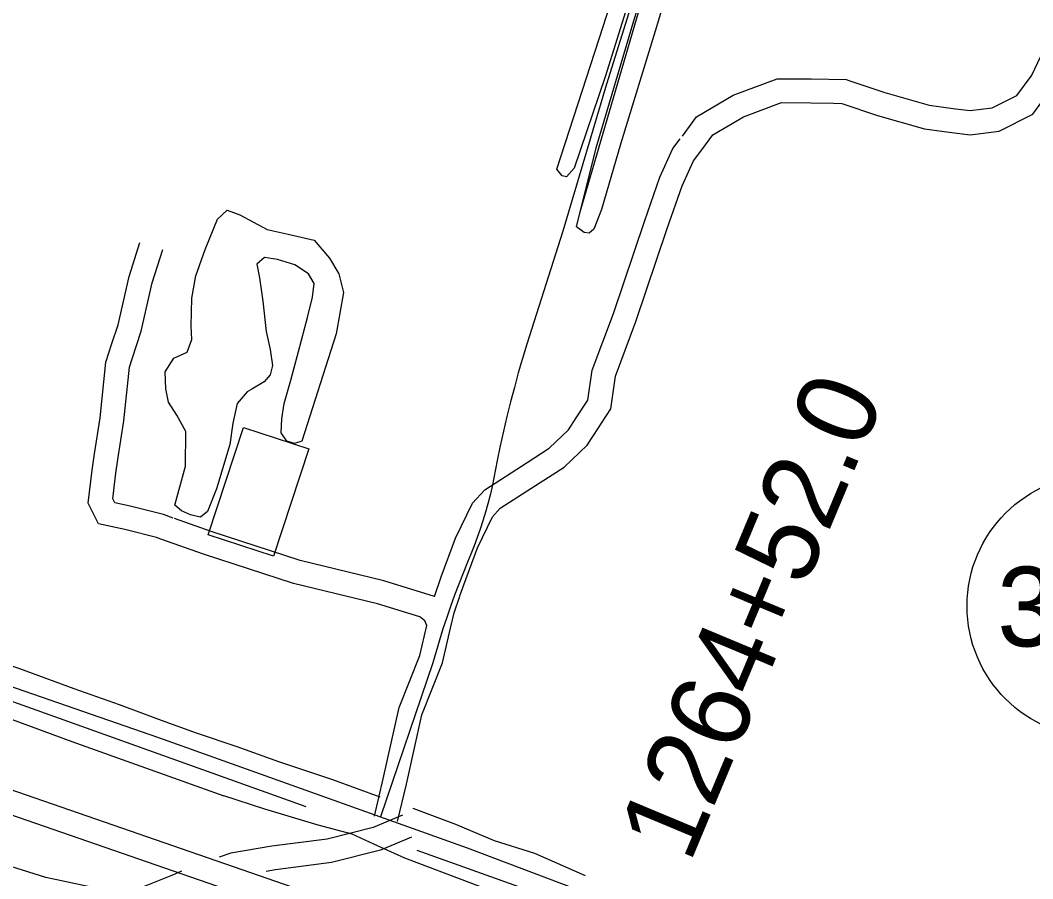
# Model space of a CAD drawing. Extents: x 3329332 to 3367211, y 631066 to 656469.
# Drawn here: x 3335657 to 3336928, y 650194 to 651272 of the extents above; entities that cross this region are included whole.
import ezdxf

# ---------------------------------------------------------------- set-up
doc = ezdxf.new("R2010")
doc.units = 0
for name, color, linetype in [('V-BLDG-OTLN', 7, 'Continuous'), ('V-DTCH-CNTR', 7, 'Continuous'), ('V-LEVE-TOET', 7, 'Continuous'), ('V-ROAD-CNTR', 7, 'Continuous'), ('V-ROAD-IDEN', 7, 'Continuous'), ('V-SITE-VEGE', 7, 'Continuous'), ('V-SURV-IDEN', 7, 'Continuous'), ('V-SURV-LINE', 7, 'Continuous'), ('V-TOPO-SHOR', 7, 'Continuous')]:
    doc.layers.add(name, color=color, linetype=linetype)

msp = doc.modelspace()

# ---------------------------------------------------------------- linework, layer by layer
at = {"layer": 'V-BLDG-OTLN'}
msp.add_lwpolyline([(3336019.4, 650733.7), (3335975.2, 650599), (3335893.1, 650626), (3335937.3, 650760.7)], close=True, dxfattribs=at)
at = {"layer": 'V-DTCH-CNTR'}
msp.add_lwpolyline([(3336472.2, 651444.9), (3336393.1, 651191.8), (3336338.4, 651007), (3336293, 650865.2), (3336287.6, 650847.2), (3336282.4, 650829), (3336277.5, 650810.9), (3336272.7, 650792.6), (3336268.2, 650774.4), (3336263.8, 650756), (3336259.7, 650737.6), (3336255.8, 650719.2), (3336253.9, 650708.2), (3336251.8, 650697.3), (3336249.5, 650686.5), (3336247, 650675.6), (3336244.2, 650664.9), (3336241.2, 650654.1), (3336238, 650643.5), (3336234.6, 650632.9), (3336230.9, 650622.4), (3336227.1, 650612), (3336223, 650601.6), (3336218.7, 650591.4), (3336213.1, 650577.6), (3336207.6, 650563.8), (3336202.4, 650549.9), (3336197.3, 650535.9), (3336192.5, 650521.9), (3336187.8, 650507.8), (3336183.3, 650493.6), (3336179.1, 650479.4), (3336175, 650465.1), (3336109.6, 650271.9)], dxfattribs=at)
at = {"layer": 'V-LEVE-TOET'}
for points in [[(3333435.4, 650905.5), (3333585.5, 650897.7), (3333679, 650879.4), (3333768.5, 650850.9), (3333895.5, 650811.2), (3334038.8, 650770.5), (3334147.6, 650739.9), (3334262.4, 650708.4), (3334325.5, 650698.2), (3334402.7, 650693.1), (3334513.5, 650701.2), (3334625.3, 650703.1), (3334696.5, 650699.1), (3334786, 650683.8), (3334902.8, 650653.2), (3335067.5, 650597.3), (3335296.2, 650516.9), (3335501.5, 650447.7), (3335722.1, 650366.3), (3335912.8, 650298.1)], [(3337615.2, 649642.5), (3337494.6, 649685.7), (3337361.8, 649739), (3337202.4, 649801.2), (3337090.8, 649845), (3336945.2, 649905.4), (3336818.8, 649959), (3336694.4, 650007.5), (3336566.9, 650058.3), (3336448, 650103.2), (3336336.5, 650145), (3336224.2, 650188.1), (3336140.1, 650219.9), (3336101.2, 650237.5), (3336073.8, 650249.9), (3336031, 650261.3), (3335964.3, 650281.5), (3335912.8, 650298.1)], [(3335931.9, 650111.7), (3335881.1, 650129), (3335824.2, 650142.3), (3335802.9, 650151.4), (3335795.2, 650156.8), (3335789.1, 650172.1), (3335771.8, 650178.2), (3335689.5, 650195.5), (3335557.3, 650237.2)]]:
    msp.add_lwpolyline(points, dxfattribs=at)
at = {"layer": 'V-ROAD-CNTR'}
for points in [[(3336926, 651201.6), (3336927, 651203), (3336950, 651251.5), (3337022.2, 651429.7), (3337051.5, 651501)], [(3336488.3, 651126.5), (3336506.2, 651150.6), (3336552.1, 651178), (3336607.4, 651198.5), (3336637.9, 651198.3)], [(3336637.9, 651198.3), (3336649.9, 651198.3), (3336693.7, 651197.4), (3336698.3, 651195.9)], [(3336831.2, 651160.7), (3336849.4, 651158.4), (3336877.1, 651161.8), (3336908.2, 651177.6), (3336926, 651201.6)], [(3336698.3, 651195.9), (3336742.3, 651181), (3336798.1, 651165.1), (3336831.2, 651160.7)], [(3336817, 651132.3), (3336849.4, 651128.1), (3336886, 651132.7), (3336928, 651154.1), (3336950.9, 651184.8)], [(3336512.9, 651109.3), (3336526.7, 651127.9), (3336565.2, 651150.8), (3336612.7, 651168.5), (3336649.5, 651168.3), (3336678.1, 651167.7)], [(3336678.1, 651167.7), (3336688.5, 651167.5), (3336733.4, 651152.4), (3336792, 651135.6), (3336817, 651132.3)], [(3336355.2, 650772.6), (3336369.7, 650794.8), (3336375.2, 650832.5), (3336401.8, 650903.7), (3336441, 651020.3), (3336460.1, 651075), (3336476.5, 651110.7), (3336485.6, 651122.9)], [(3336376.7, 650750.7), (3336398.4, 650783.9), (3336404.4, 650825), (3336430, 650893.7), (3336469.4, 651010.6), (3336488, 651063.8), (3336502.4, 651095.3), (3336512.9, 651109.3)], [(3335772.3, 650866.1), (3335780, 650889.6), (3335794.1, 650950), (3335807.5, 650992.9)], [(3335797.6, 650846.7), (3335808.9, 650881.5), (3335823, 650942.1), (3335836.1, 650983.9)], [(3335750.5, 650727.5), (3335757.4, 650772.9), (3335764.7, 650842.6), (3335772.3, 650866.1)], [(3335779.8, 650720.5), (3335787.1, 650769.1), (3335794.2, 650836.3), (3335797.6, 650846.7)], [(3336177.1, 650548.5), (3336185.7, 650573.2), (3336203.7, 650621.5), (3336225.1, 650665.5), (3336240.3, 650682.2), (3336293.6, 650716.5), (3336321.1, 650734.5), (3336345.5, 650757.8), (3336355.2, 650772.6)], [(3336209.2, 650549.4), (3336214, 650563.1), (3336231.3, 650609.7), (3336250.2, 650648.5), (3336259.8, 650659.1), (3336310, 650691.4), (3336339.8, 650710.9), (3336368.7, 650738.4), (3336376.7, 650750.7)], [(3335833.9, 650620.5), (3335828.4, 650622.5), (3335788.4, 650632.5), (3335755.4, 650639.8), (3335742.6, 650665.7), (3335747.5, 650707.1), (3335750.5, 650727.5)], [(3335849.4, 650646.8), (3335837.1, 650651.2), (3335795.3, 650661.8), (3335775.9, 650666), (3335773.4, 650671), (3335777.2, 650703.1), (3335779.8, 650720.5)], [(3336177.1, 650548.5), (3336113.8, 650568.2), (3336008.6, 650593.7), (3335897.1, 650630), (3335850.8, 650646.3)], [(3336167.4, 650512.1), (3336165, 650517.7), (3336158.9, 650522.7), (3336105.8, 650539.3), (3336000.4, 650564.8), (3335887.4, 650601.6), (3335833.9, 650620.5)], [(3336197.3, 650508.5), (3336201.8, 650527.9), (3336208.9, 650548.6)], [(3336101.7, 650272.8), (3336112.7, 650319.4), (3336132.8, 650408.9), (3336158.7, 650474.3), (3336167.4, 650512.1)], [(3335451.3, 650502.7), (3335830.6, 650371.5), (3336218.2, 650233), (3336467.3, 650138.8), (3336816.5, 649992.3), (3337213.1, 649826.6), (3337406.7, 649751.6), (3337593.6, 649680.4), (3337678.1, 649661.1), (3337748.8, 649653.3), (3337841.3, 649661.7), (3337945.8, 649680.7), (3338033, 649708.3), (3338176, 649751.6), (3338247.1, 649768.4), (3338321.6, 649777.5), (3338384.8, 649776.3), (3338442.4, 649772.8), (3338528.8, 649753.9), (3338662.7, 649722.5), (3338806.5, 649687.4), (3338886.3, 649663.5), (3338953.2, 649639), (3339090.7, 649573.2)], [(3336130.9, 650265.9), (3336141.9, 650312.7), (3336161.5, 650400), (3336187.4, 650465.3), (3336197.3, 650508.5)], [(3336136.9, 650273.8), (3336100.1, 650258.3), (3336042.3, 650243.8), (3335973.1, 650235), (3335921.7, 650226.1), (3335906.8, 650221.3)], [(3336148.5, 650246.1), (3336109.6, 650229.7), (3336047.9, 650214.3), (3335977.5, 650205.3), (3335966.1, 650203.3)], [(3335859.6, 650203.5), (3335848.3, 650198.7), (3335796, 650177.4), (3335761.3, 650158.2), (3335725, 650098.3), (3335714.4, 650049.1), (3335694.7, 649992.4), (3335669.3, 649907.9), (3335658.9, 649866.1)]]:
    msp.add_lwpolyline(points, dxfattribs=at)
at = {"layer": 'V-ROAD-IDEN'}
msp.add_circle((3337010.6, 650536.4), 165, dxfattribs=at)
at = {"layer": 'V-SITE-VEGE'}
for points in [[(3336527, 651639.6), (3336456.8, 651410.2), (3336391.5, 651200.7), (3336352.4, 651086.1), (3336342.9, 651075.4), (3336337.3, 651076.6), (3336330.6, 651085), (3336383.8, 651248.7), (3336432.6, 651398.9), (3336477.8, 651547.6), (3336508.5, 651647.2)], [(3336567.4, 651628.2), (3336539.9, 651536.9), (3336500.8, 651412.8), (3336454, 651258.2), (3336411.2, 651117.4), (3336386.6, 651034.4), (3336377.3, 651009.5), (3336371.4, 651004.7), (3336365, 651005.6), (3336355.6, 651012.4), (3336380.3, 651111.6), (3336428.3, 651274.2), (3336498.9, 651499.1), (3336542.9, 651639.1)], [(3335851.5, 650663), (3335864.7, 650711.9), (3335865.3, 650755.5), (3335853.7, 650775.9), (3335843.2, 650792.5), (3335840.1, 650809), (3335839.1, 650830.5), (3335850.2, 650847.7), (3335866.7, 650855.1), (3335872.7, 650871.1), (3335871.6, 650888), (3335872.6, 650922.9), (3335877.8, 650951.1), (3335889.4, 650984), (3335904.9, 651022), (3335917.1, 651033.6), (3335932.8, 651027.7), (3335967.2, 651009.1), (3335993.4, 651003.4), (3336026.3, 650995.8), (3336045.4, 650973.3), (3336057.1, 650953.6), (3336062.8, 650930.1), (3336053.9, 650878.3), (3336010.8, 650743.3), (3336001.4, 650740.5), (3335991.8, 650743.4), (3335984.6, 650754), (3335985.4, 650771.3), (3335988.7, 650790.9), (3335996.7, 650820.2), (3336006.7, 650855.9), (3336017.9, 650898.6), (3336024, 650924), (3336026, 650941.3), (3336019, 650953.5), (3336001.8, 650964.9), (3335980.3, 650971.3), (3335963.8, 650974.2), (3335954.4, 650965.6), (3335957.4, 650948.3), (3335961.6, 650919.3), (3335966.1, 650881.2), (3335971, 650858.4), (3335973.7, 650838.4), (3335970.8, 650826.7), (3335963.3, 650817.7), (3335948, 650808.7), (3335942.1, 650805.2), (3335929.5, 650790.8), (3335924.2, 650766.1), (3335920.5, 650739.1), (3335903.8, 650683.5), (3335892.2, 650655.3), (3335883.5, 650647.9), (3335871, 650651.1), (3335859.7, 650655.9)]]:
    msp.add_lwpolyline(points, close=True, dxfattribs=at)
at = {"layer": 'V-SURV-LINE'}
for points in [[(3334758.2, 650613.1), (3336366.8, 650056.1)], [(3336356.9, 650027.7), (3334748.4, 650584.8)]]:
    msp.add_lwpolyline(points, dxfattribs=at)
at = {"layer": 'V-TOPO-SHOR'}
msp.add_line((3336360.2, 651031.2), (3336851.7, 652719.6), dxfattribs=at)
for points in [[(3336016.3, 650284.3), (3335604.3, 650431.8), (3335370.6, 650516.5), (3335151.2, 650587.1), (3334852.8, 650690.7), (3334590.8, 650773.8), (3334475.5, 650808.3), (3334396.6, 650828.7), (3334357.8, 650837.2)], [(3335576.8, 650484.3), (3335656.3, 650458.1), (3335724.6, 650432.8), (3335781.6, 650412.9), (3335834.3, 650393), (3335878.1, 650377.4), (3335929.1, 650360.2)], [(3335929.1, 650360.2), (3335981.5, 650341.3), (3336049.1, 650318.6), (3336108.5, 650296.8)], [(3336150.1, 650282.5), (3336203.7, 650262.4), (3336252.3, 650241.9), (3336302.6, 650226.3), (3336366.5, 650198.3)], [(3337558.9, 649668.7), (3337219.4, 649802.2), (3336949.4, 649916.9), (3336655.8, 650039.4), (3336283.2, 650183.8), (3336155.3, 650229.3)]]:
    msp.add_lwpolyline(points, dxfattribs=at)

# ---------------------------------------------------------------- texts
at = {"layer": 'V-ROAD-IDEN'}
msp.add_text('327', height=100, rotation=0.3915, dxfattribs=at).set_placement((3336883.7, 650485.5))
at = {"layer": 'V-SURV-IDEN'}
msp.add_text('1264+52.0', height=100, rotation=67.3383, dxfattribs=at).set_placement((3336497.6, 650211.9))

doc.saveas('drawing.dxf')
